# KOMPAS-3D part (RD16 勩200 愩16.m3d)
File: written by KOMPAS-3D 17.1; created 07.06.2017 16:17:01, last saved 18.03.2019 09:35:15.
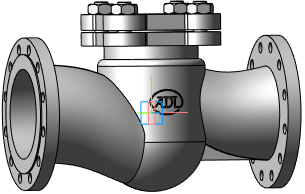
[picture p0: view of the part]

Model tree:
1. Операция без истории:2  (labels: Сталь 20  ГОСТ 1050-88)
